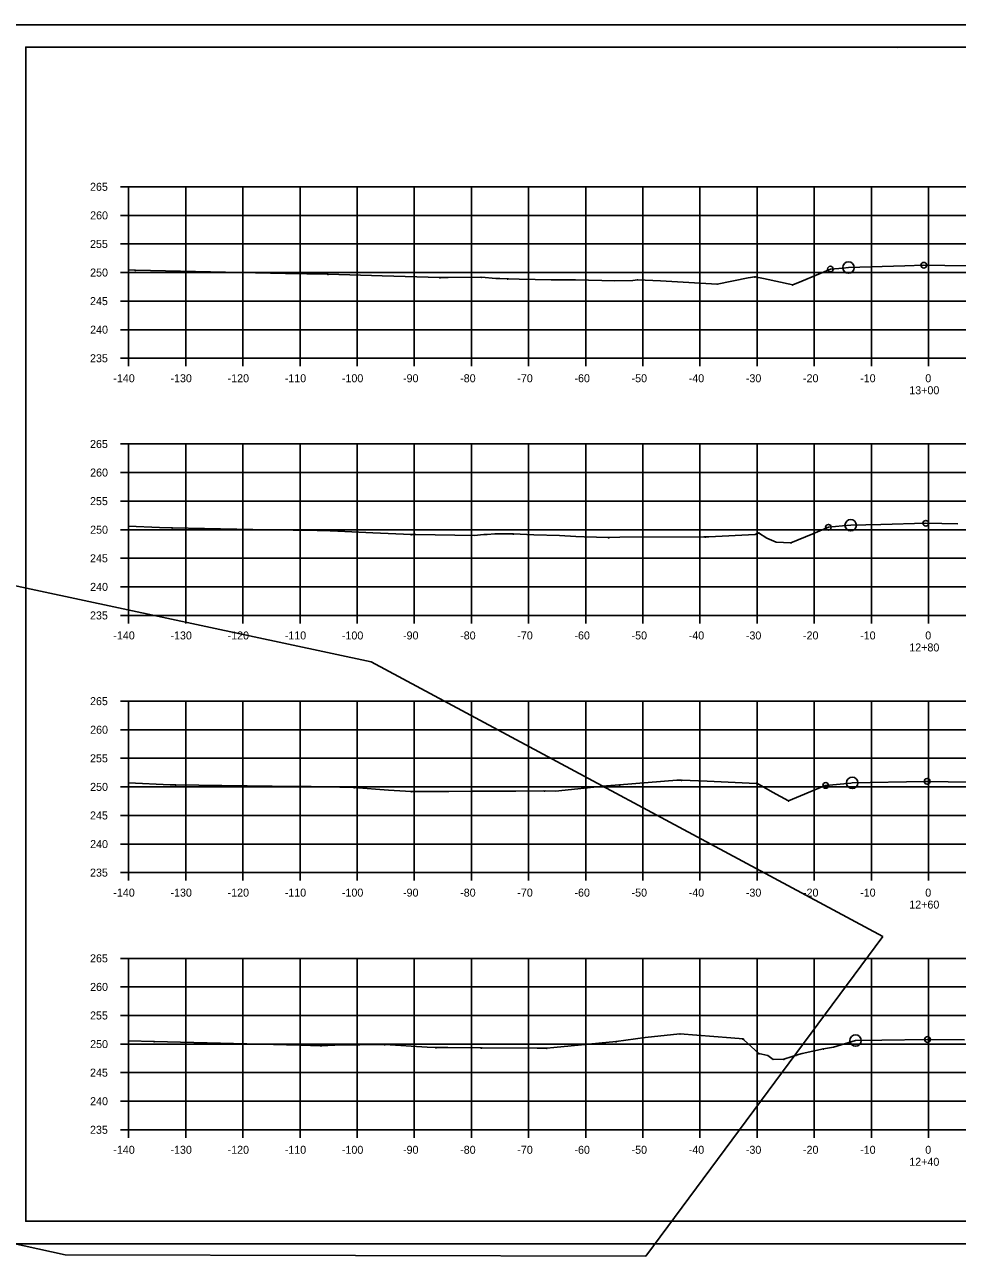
# Model space of a CAD drawing. Extents: x 1300404 to 1323571, y 234004 to 252077.
# Drawn here: x 1315559.1 to 1315722.3, y 244045.5 to 244261.8 of the extents above; entities that cross this region are included whole.
import ezdxf

# ---------------------------------------------------------------- set-up
doc = ezdxf.new("R2010")
doc.units = 0
for name, color, linetype in [('Default', 7, 'Continuous'), ('R_Axis', 7, 'Continuous'), ('R_Axis Annot', 7, 'Continuous'), ('R_Border', 7, 'Continuous'), ('R_Draft', 7, 'Continuous'), ('R_Exist Surface', 7, 'Continuous'), ('R_Flooplain', 7, 'Continuous'), ('R_Grid', 7, 'Continuous'), ('R_No Plot', 7, 'Continuous')]:
    doc.layers.add(name, color=color, linetype=linetype)

msp = doc.modelspace()

# ---------------------------------------------------------------- linework, layer by layer
at = {"layer": 'Default'}
for p, q in [((1315559.28, 244257.94), (1315875.46, 244257.94)), ((1315559.28, 244052.48), (1315559.28, 244257.94)), ((1315875.46, 244052.48), (1315559.28, 244052.48))]:
    msp.add_line(p, q, dxfattribs=at)
at = {"layer": 'R_Axis'}
for p, q in [((1315575.88, 244233.48), (1315577.28, 244233.48)), ((1315577.28, 244203.48), (1315577.28, 244233.48)), ((1315575.88, 244228.48), (1315577.28, 244228.48)), ((1315575.88, 244223.48), (1315577.28, 244223.48)), ((1315575.88, 244218.48), (1315577.28, 244218.48)), ((1315575.88, 244213.48), (1315577.28, 244213.48)), ((1315575.88, 244208.48), (1315577.28, 244208.48)), ((1315575.88, 244203.48), (1315577.28, 244203.48)), ((1315577.28, 244203.48), (1315857.28, 244203.48)), ((1315577.28, 244202.08), (1315577.28, 244203.48)), ((1315587.28, 244202.08), (1315587.28, 244203.48)), ((1315597.28, 244202.08), (1315597.28, 244203.48)), ((1315607.28, 244202.08), (1315607.28, 244203.48)), ((1315617.28, 244202.08), (1315617.28, 244203.48)), ((1315627.28, 244202.08), (1315627.28, 244203.48)), ((1315637.28, 244202.08), (1315637.28, 244203.48)), ((1315647.28, 244202.08), (1315647.28, 244203.48)), ((1315657.28, 244202.08), (1315657.28, 244203.48)), ((1315667.28, 244202.08), (1315667.28, 244203.48)), ((1315677.28, 244202.08), (1315677.28, 244203.48)), ((1315687.28, 244202.08), (1315687.28, 244203.48)), ((1315697.28, 244202.08), (1315697.28, 244203.48)), ((1315707.28, 244202.08), (1315707.28, 244203.48)), ((1315717.28, 244202.08), (1315717.28, 244203.48)), ((1315575.88, 244188.48), (1315577.28, 244188.48)), ((1315577.28, 244158.48), (1315577.28, 244188.48)), ((1315575.88, 244183.48), (1315577.28, 244183.48)), ((1315575.88, 244178.48), (1315577.28, 244178.48)), ((1315575.88, 244173.48), (1315577.28, 244173.48)), ((1315575.88, 244168.48), (1315577.28, 244168.48)), ((1315575.88, 244163.48), (1315577.28, 244163.48)), ((1315575.88, 244158.48), (1315577.28, 244158.48)), ((1315577.28, 244158.48), (1315857.28, 244158.48)), ((1315577.28, 244157.08), (1315577.28, 244158.48)), ((1315587.28, 244157.08), (1315587.28, 244158.48)), ((1315597.28, 244157.08), (1315597.28, 244158.48)), ((1315607.28, 244157.08), (1315607.28, 244158.48)), ((1315617.28, 244157.08), (1315617.28, 244158.48)), ((1315627.28, 244157.08), (1315627.28, 244158.48)), ((1315637.28, 244157.08), (1315637.28, 244158.48)), ((1315647.28, 244157.08), (1315647.28, 244158.48)), ((1315657.28, 244157.08), (1315657.28, 244158.48)), ((1315667.28, 244157.08), (1315667.28, 244158.48)), ((1315677.28, 244157.08), (1315677.28, 244158.48)), ((1315687.28, 244157.08), (1315687.28, 244158.48)), ((1315697.28, 244157.08), (1315697.28, 244158.48)), ((1315707.28, 244157.08), (1315707.28, 244158.48)), ((1315717.28, 244157.08), (1315717.28, 244158.48)), ((1315575.88, 244143.48), (1315577.28, 244143.48)), ((1315577.28, 244113.48), (1315577.28, 244143.48)), ((1315575.88, 244138.48), (1315577.28, 244138.48)), ((1315575.88, 244133.48), (1315577.28, 244133.48)), ((1315575.88, 244128.48), (1315577.28, 244128.48)), ((1315575.88, 244123.48), (1315577.28, 244123.48)), ((1315575.88, 244118.48), (1315577.28, 244118.48)), ((1315575.88, 244113.48), (1315577.28, 244113.48)), ((1315577.28, 244113.48), (1315857.28, 244113.48)), ((1315577.28, 244112.08), (1315577.28, 244113.48)), ((1315587.28, 244112.08), (1315587.28, 244113.48)), ((1315597.28, 244112.08), (1315597.28, 244113.48)), ((1315607.28, 244112.08), (1315607.28, 244113.48)), ((1315617.28, 244112.08), (1315617.28, 244113.48)), ((1315627.28, 244112.08), (1315627.28, 244113.48)), ((1315637.28, 244112.08), (1315637.28, 244113.48)), ((1315647.28, 244112.08), (1315647.28, 244113.48)), ((1315657.28, 244112.08), (1315657.28, 244113.48)), ((1315667.28, 244112.08), (1315667.28, 244113.48)), ((1315677.28, 244112.08), (1315677.28, 244113.48)), ((1315687.28, 244112.08), (1315687.28, 244113.48)), ((1315697.28, 244112.08), (1315697.28, 244113.48)), ((1315707.28, 244112.08), (1315707.28, 244113.48)), ((1315717.28, 244112.08), (1315717.28, 244113.48)), ((1315575.88, 244098.48), (1315577.28, 244098.48)), ((1315577.28, 244068.48), (1315577.28, 244098.48)), ((1315575.88, 244093.48), (1315577.28, 244093.48)), ((1315575.88, 244088.48), (1315577.28, 244088.48)), ((1315575.88, 244083.48), (1315577.28, 244083.48)), ((1315575.88, 244078.48), (1315577.28, 244078.48)), ((1315575.88, 244073.48), (1315577.28, 244073.48)), ((1315575.88, 244068.48), (1315577.28, 244068.48)), ((1315577.28, 244068.48), (1315857.28, 244068.48)), ((1315577.28, 244067.08), (1315577.28, 244068.48)), ((1315587.28, 244067.08), (1315587.28, 244068.48)), ((1315597.28, 244067.08), (1315597.28, 244068.48)), ((1315607.28, 244067.08), (1315607.28, 244068.48)), ((1315617.28, 244067.08), (1315617.28, 244068.48)), ((1315627.28, 244067.08), (1315627.28, 244068.48)), ((1315637.28, 244067.08), (1315637.28, 244068.48)), ((1315647.28, 244067.08), (1315647.28, 244068.48)), ((1315657.28, 244067.08), (1315657.28, 244068.48)), ((1315667.28, 244067.08), (1315667.28, 244068.48)), ((1315677.28, 244067.08), (1315677.28, 244068.48)), ((1315687.28, 244067.08), (1315687.28, 244068.48)), ((1315697.28, 244067.08), (1315697.28, 244068.48)), ((1315707.28, 244067.08), (1315707.28, 244068.48)), ((1315717.28, 244067.08), (1315717.28, 244068.48))]:
    msp.add_line(p, q, dxfattribs=at)
at = {"layer": 'R_Border'}
for p, q in [((1315711.8, 244257.68), (1315711.8, 244257.68)), ((1315711.8, 244257.68), (1315711.8, 244257.68)), ((1315559.28, 244052.48), (1315559.28, 244052.48))]:
    msp.add_line(p, q, dxfattribs=at)
at = {"layer": 'R_Draft'}
for points in [[(1315578.48, 244218.92), (1315578.53, 244218.82), (1315578.43, 244218.82)], [(1315612.18, 244218.23), (1315612.23, 244218.13), (1315612.13, 244218.13)], [(1315639.02, 244217.73), (1315639.07, 244217.63), (1315638.97, 244217.63)], [(1315686.89, 244217.78), (1315686.94, 244217.68), (1315686.84, 244217.68)], [(1315631.78, 244217.65), (1315631.83, 244217.55), (1315631.73, 244217.55)], [(1315643.59, 244217.42), (1315643.64, 244217.32), (1315643.54, 244217.32)], [(1315666.36, 244217.28), (1315666.41, 244217.18), (1315666.31, 244217.18)], [(1315680.29, 244216.52), (1315680.34, 244216.42), (1315680.24, 244216.42)], [(1315693.51, 244216.37), (1315693.56, 244216.27), (1315693.46, 244216.27)], [(1315584.89, 244173.85), (1315584.94, 244173.75), (1315584.84, 244173.75)], [(1315612.66, 244173.36), (1315612.71, 244173.26), (1315612.61, 244173.26)], [(1315626.72, 244172.7), (1315626.77, 244172.6), (1315626.67, 244172.6)], [(1315644.61, 244172.79), (1315644.66, 244172.69), (1315644.56, 244172.69)], [(1315687.52, 244172.98), (1315687.57, 244172.88), (1315687.47, 244172.88)], [(1315661.32, 244172.15), (1315661.37, 244172.05), (1315661.27, 244172.05)], [(1315678.21, 244172.26), (1315678.26, 244172.16), (1315678.16, 244172.16)], [(1315693.21, 244171.24), (1315693.26, 244171.14), (1315693.16, 244171.14)], [(1315674.06, 244129.72), (1315674.11, 244129.62), (1315674.01, 244129.62)], [(1315687.21, 244129.17), (1315687.26, 244129.07), (1315687.16, 244129.07)], [(1315585.52, 244128.88), (1315585.57, 244128.78), (1315585.47, 244128.78)], [(1315606.86, 244128.62), (1315606.91, 244128.52), (1315606.81, 244128.52)], [(1315616.76, 244128.41), (1315616.81, 244128.31), (1315616.71, 244128.31)], [(1315626.73, 244127.72), (1315626.78, 244127.62), (1315626.68, 244127.62)], [(1315637.37, 244127.76), (1315637.42, 244127.66), (1315637.32, 244127.66)], [(1315650.06, 244127.86), (1315650.11, 244127.76), (1315650.01, 244127.76)], [(1315663.21, 244128.88), (1315663.26, 244128.78), (1315663.16, 244128.78)], [(1315692.79, 244126.11), (1315692.84, 244126.01), (1315692.74, 244126.01)], [(1315581.76, 244083.97), (1315581.81, 244083.87), (1315581.71, 244083.87)], [(1315662.6, 244083.97), (1315662.65, 244083.87), (1315662.55, 244083.87)], [(1315673.78, 244085.33), (1315673.83, 244085.23), (1315673.73, 244085.23)], [(1315684.81, 244084.43), (1315684.86, 244084.33), (1315684.76, 244084.33)], [(1315610.96, 244083.24), (1315611.01, 244083.14), (1315610.91, 244083.14)], [(1315622.11, 244083.44), (1315622.16, 244083.34), (1315622.06, 244083.34)], [(1315631.07, 244082.91), (1315631.12, 244082.81), (1315631.02, 244082.81)], [(1315639.03, 244082.85), (1315639.08, 244082.75), (1315638.98, 244082.75)], [(1315650.48, 244082.83), (1315650.53, 244082.73), (1315650.43, 244082.73)], [(1315687.59, 244081.87), (1315687.64, 244081.77), (1315687.54, 244081.77)], [(1315694.12, 244081.59), (1315694.17, 244081.49), (1315694.07, 244081.49)], [(1315698.88, 244082.69), (1315698.93, 244082.59), (1315698.83, 244082.59)], [(1315691.95, 244080.86), (1315692, 244080.76), (1315691.9, 244080.76)]]:
    msp.add_lwpolyline(points, close=True, dxfattribs=at)
at = {"layer": 'R_Exist Surface'}
for points in [[(1315577.28, 244218.95), (1315578.48, 244218.87), (1315604.76, 244218.32), (1315612.18, 244218.18), (1315621.64, 244217.88), (1315631.78, 244217.6), (1315633.19, 244217.63), (1315639.02, 244217.68), (1315641.54, 244217.46), (1315642.25, 244217.44), (1315643.59, 244217.37), (1315643.78, 244217.36), (1315645.61, 244217.34), (1315651.21, 244217.22), (1315655.49, 244217.23), (1315662.35, 244217.02), (1315665.5, 244217.08), (1315666.36, 244217.23), (1315670.35, 244217), (1315680.29, 244216.47), (1315685.72, 244217.53), (1315686.89, 244217.73), (1315688.41, 244217.43), (1315693.51, 244216.32), (1315695.08, 244216.97), (1315700.1, 244219.08), (1315702.31, 244219.26), (1315703.27, 244219.35), (1315713.11, 244219.67), (1315716.46, 244219.76), (1315727.52, 244219.61)], [(1315577.28, 244174.08), (1315582.68, 244173.84), (1315584.89, 244173.8), (1315601.88, 244173.46), (1315610.26, 244173.33), (1315612.66, 244173.31), (1315620.03, 244172.91), (1315626.72, 244172.65), (1315627.57, 244172.64), (1315637.77, 244172.49), (1315639.45, 244172.62), (1315640.02, 244172.63), (1315641.38, 244172.77), (1315644.61, 244172.74), (1315648.21, 244172.6), (1315652.7, 244172.44), (1315655.55, 244172.28), (1315657, 244172.25), (1315661.32, 244172.1), (1315663.25, 244172.2), (1315677.96, 244172.21), (1315678.21, 244172.21), (1315678.84, 244172.24), (1315686.93, 244172.62), (1315687.52, 244172.93), (1315688.99, 244172), (1315690.64, 244171.3), (1315693.21, 244171.19), (1315697.05, 244172.78), (1315699.75, 244173.9), (1315702.24, 244174.14), (1315703.66, 244174.26), (1315708.93, 244174.41), (1315716.8, 244174.6), (1315722.41, 244174.52)], [(1315577.28, 244129.17), (1315584.54, 244128.84), (1315585.52, 244128.83), (1315593.57, 244128.71), (1315606.86, 244128.57), (1315609.21, 244128.55), (1315616.76, 244128.36), (1315622.74, 244127.91), (1315626.73, 244127.67), (1315633.3, 244127.68), (1315637.37, 244127.71), (1315645.08, 244127.76), (1315650.06, 244127.81), (1315652, 244127.71), (1315660.91, 244128.68), (1315663.21, 244128.83), (1315673.22, 244129.63), (1315674.06, 244129.67), (1315678.53, 244129.49), (1315687.1, 244129.07), (1315687.21, 244129.12), (1315690, 244127.55), (1315692.79, 244126.06), (1315698.81, 244128.53), (1315699.28, 244128.73), (1315703.66, 244129.15), (1315703.93, 244129.18), (1315716.55, 244129.44), (1315717.03, 244129.45), (1315717.54, 244129.44), (1315730.12, 244129.21)], [(1315577.28, 244084.03), (1315581.76, 244083.92), (1315607.26, 244083.29), (1315610.96, 244083.19), (1315613.4, 244083.26), (1315622.11, 244083.39), (1315629.53, 244082.95), (1315631.07, 244082.86), (1315633.13, 244082.89), (1315639.03, 244082.8), (1315648.8, 244082.76), (1315650.48, 244082.78), (1315651.73, 244082.87), (1315662.6, 244083.92), (1315667.67, 244084.63), (1315673.78, 244085.28), (1315682.69, 244084.57), (1315684.81, 244084.38), (1315684.98, 244084.21), (1315687.59, 244081.82), (1315689.13, 244081.46), (1315690.07, 244080.8), (1315691.95, 244080.81), (1315693.44, 244081.28), (1315694.12, 244081.54), (1315695.15, 244081.82), (1315698.88, 244082.64), (1315700.64, 244082.95), (1315704.51, 244084.09), (1315709.1, 244084.15), (1315717.1, 244084.28), (1315723.6, 244084.2)]]:
    msp.add_lwpolyline(points, dxfattribs=at)
at = {"layer": 'R_Flooplain'}
for p, q in [((1315471.31, 244182.06), (1315619.74, 244150.39)), ((1315619.74, 244150.39), (1315709.29, 244102.32)), ((1315709.29, 244102.32), (1315667.79, 244046.34)), ((1315566.18, 244046.62), (1315451.3, 244071.77)), ((1315667.79, 244046.34), (1315566.18, 244046.62))]:
    msp.add_line(p, q, dxfattribs=at)
at = {"layer": 'R_Grid'}
for p, q in [((1315577.28, 244233.48), (1315857.28, 244233.48)), ((1315577.28, 244203.48), (1315577.28, 244233.48)), ((1315587.28, 244203.48), (1315587.28, 244233.48)), ((1315597.28, 244203.48), (1315597.28, 244233.48)), ((1315607.28, 244203.48), (1315607.28, 244233.48)), ((1315617.28, 244203.48), (1315617.28, 244233.48)), ((1315627.28, 244203.48), (1315627.28, 244233.48)), ((1315637.28, 244203.48), (1315637.28, 244233.48)), ((1315647.28, 244203.48), (1315647.28, 244233.48)), ((1315657.28, 244203.48), (1315657.28, 244233.48)), ((1315667.28, 244203.48), (1315667.28, 244233.48)), ((1315677.28, 244203.48), (1315677.28, 244233.48)), ((1315687.28, 244203.48), (1315687.28, 244233.48)), ((1315697.28, 244203.48), (1315697.28, 244233.48)), ((1315707.28, 244203.48), (1315707.28, 244233.48)), ((1315717.28, 244203.48), (1315717.28, 244233.48)), ((1315577.28, 244228.48), (1315857.28, 244228.48)), ((1315577.28, 244223.48), (1315857.28, 244223.48)), ((1315577.28, 244218.48), (1315857.28, 244218.48)), ((1315577.28, 244213.48), (1315857.28, 244213.48)), ((1315577.28, 244208.48), (1315857.28, 244208.48)), ((1315577.28, 244203.48), (1315857.28, 244203.48)), ((1315577.28, 244188.48), (1315857.28, 244188.48)), ((1315577.28, 244158.48), (1315577.28, 244188.48)), ((1315587.28, 244158.48), (1315587.28, 244188.48)), ((1315597.28, 244158.48), (1315597.28, 244188.48)), ((1315607.28, 244158.48), (1315607.28, 244188.48)), ((1315617.28, 244158.48), (1315617.28, 244188.48)), ((1315627.28, 244158.48), (1315627.28, 244188.48)), ((1315637.28, 244158.48), (1315637.28, 244188.48)), ((1315647.28, 244158.48), (1315647.28, 244188.48)), ((1315657.28, 244158.48), (1315657.28, 244188.48)), ((1315667.28, 244158.48), (1315667.28, 244188.48)), ((1315677.28, 244158.48), (1315677.28, 244188.48)), ((1315687.28, 244158.48), (1315687.28, 244188.48)), ((1315697.28, 244158.48), (1315697.28, 244188.48)), ((1315707.28, 244158.48), (1315707.28, 244188.48)), ((1315717.28, 244158.48), (1315717.28, 244188.48)), ((1315577.28, 244183.48), (1315857.28, 244183.48)), ((1315577.28, 244178.48), (1315857.28, 244178.48)), ((1315577.28, 244173.48), (1315857.28, 244173.48)), ((1315577.28, 244168.48), (1315857.28, 244168.48)), ((1315577.28, 244163.48), (1315857.28, 244163.48)), ((1315577.28, 244158.48), (1315857.28, 244158.48)), ((1315577.28, 244143.48), (1315857.28, 244143.48)), ((1315577.28, 244113.48), (1315577.28, 244143.48)), ((1315587.28, 244113.48), (1315587.28, 244143.48)), ((1315597.28, 244113.48), (1315597.28, 244143.48)), ((1315607.28, 244113.48), (1315607.28, 244143.48)), ((1315617.28, 244113.48), (1315617.28, 244143.48)), ((1315627.28, 244113.48), (1315627.28, 244143.48)), ((1315637.28, 244113.48), (1315637.28, 244143.48)), ((1315647.28, 244113.48), (1315647.28, 244143.48)), ((1315657.28, 244113.48), (1315657.28, 244143.48)), ((1315667.28, 244113.48), (1315667.28, 244143.48)), ((1315677.28, 244113.48), (1315677.28, 244143.48)), ((1315687.28, 244113.48), (1315687.28, 244143.48)), ((1315697.28, 244113.48), (1315697.28, 244143.48)), ((1315707.28, 244113.48), (1315707.28, 244143.48)), ((1315717.28, 244113.48), (1315717.28, 244143.48)), ((1315577.28, 244138.48), (1315857.28, 244138.48)), ((1315577.28, 244133.48), (1315857.28, 244133.48)), ((1315577.28, 244128.48), (1315857.28, 244128.48)), ((1315577.28, 244123.48), (1315857.28, 244123.48)), ((1315577.28, 244118.48), (1315857.28, 244118.48)), ((1315577.28, 244113.48), (1315857.28, 244113.48)), ((1315577.28, 244098.48), (1315857.28, 244098.48)), ((1315577.28, 244068.48), (1315577.28, 244098.48)), ((1315587.28, 244068.48), (1315587.28, 244098.48)), ((1315597.28, 244068.48), (1315597.28, 244098.48)), ((1315607.28, 244068.48), (1315607.28, 244098.48)), ((1315617.28, 244068.48), (1315617.28, 244098.48)), ((1315627.28, 244068.48), (1315627.28, 244098.48)), ((1315637.28, 244068.48), (1315637.28, 244098.48)), ((1315647.28, 244068.48), (1315647.28, 244098.48)), ((1315657.28, 244068.48), (1315657.28, 244098.48)), ((1315667.28, 244068.48), (1315667.28, 244098.48)), ((1315677.28, 244068.48), (1315677.28, 244098.48)), ((1315687.28, 244068.48), (1315687.28, 244098.48)), ((1315697.28, 244068.48), (1315697.28, 244098.48)), ((1315707.28, 244068.48), (1315707.28, 244098.48)), ((1315717.28, 244068.48), (1315717.28, 244098.48)), ((1315577.28, 244093.48), (1315857.28, 244093.48)), ((1315577.28, 244088.48), (1315857.28, 244088.48)), ((1315577.28, 244083.48), (1315857.28, 244083.48)), ((1315577.28, 244078.48), (1315857.28, 244078.48)), ((1315577.28, 244073.48), (1315857.28, 244073.48)), ((1315577.28, 244068.48), (1315857.28, 244068.48))]:
    msp.add_line(p, q, dxfattribs=at)
at = {"layer": 'R_No Plot'}
for p, q in [((1315546.87, 244261.84), (1315880.21, 244261.84)), ((1315546.87, 244048.51), (1315880.21, 244048.51)), ((1315546.87, 244048.5), (1315880.21, 244048.5))]:
    msp.add_line(p, q, dxfattribs=at)
for points in [[(1315546.87, 244261.84), (1315880.21, 244261.84), (1315880.21, 244048.5), (1315546.87, 244048.5)], [(1315793.2, 244257.94), (1315793.2, 244248.06), (1315828.93, 244248.06), (1315828.93, 244245.14), (1315852.13, 244245.14), (1315852.13, 244223.03), (1315875.46, 244223.03), (1315875.46, 244052.48), (1315559.28, 244052.48), (1315559.28, 244257.94)], [(1315546.87, 244048.5), (1315880.21, 244048.5), (1315880.21, 243835.16), (1315546.87, 243835.16)]]:
    msp.add_lwpolyline(points, close=True, dxfattribs=at)
for centre, radius in [((1315703.27, 244219.35), 1), ((1315716.46, 244219.76), 0.5), ((1315700.1, 244219.08), 0.5), ((1315703.66, 244174.26), 1), ((1315716.8, 244174.6), 0.5), ((1315699.75, 244173.9), 0.5), ((1315699.28, 244128.73), 0.5), ((1315703.93, 244129.18), 1), ((1315717.03, 244129.45), 0.5), ((1315704.51, 244084.09), 1), ((1315717.1, 244084.28), 0.5)]:
    msp.add_circle(centre, radius, dxfattribs=at)

# ---------------------------------------------------------------- texts
at = {"layer": 'R_Axis'}
for p in [(1315577.28, 244203.48), (1315577.28, 244158.48), (1315577.28, 244113.48), (1315577.28, 244068.48)]:
    msp.add_text('-', height=0.0001, dxfattribs=at).set_placement(p)
at = {"layer": 'R_Axis Annot'}
for s, p in [('265', (1315570.53, 244232.78)), ('260', (1315570.55, 244227.78)), ('255', (1315570.53, 244222.78)), ('250', (1315570.55, 244217.78)), ('245', (1315570.53, 244212.78)), ('240', (1315570.55, 244207.78)), ('235', (1315570.53, 244202.78)), ('-140', (1315574.61, 244199.28)), ('-130', (1315584.61, 244199.28)), ('-120', (1315594.61, 244199.28)), ('-110', (1315604.61, 244199.28)), ('-100', (1315614.61, 244199.28)), ('-90', (1315625.31, 244199.28)), ('-80', (1315635.31, 244199.28)), ('-70', (1315645.31, 244199.28)), ('-60', (1315655.31, 244199.28)), ('-50', (1315665.31, 244199.28)), ('-40', (1315675.31, 244199.28)), ('-30', (1315685.31, 244199.28)), ('-20', (1315695.31, 244199.28)), ('-10', (1315705.31, 244199.28)), ('0', (1315716.71, 244199.28)), ('13+00', (1315713.91, 244197.18)), ('265', (1315570.53, 244187.78)), ('260', (1315570.55, 244182.78)), ('255', (1315570.53, 244177.78)), ('250', (1315570.55, 244172.78)), ('245', (1315570.53, 244167.78)), ('240', (1315570.55, 244162.78)), ('235', (1315570.53, 244157.78)), ('-140', (1315574.61, 244154.28)), ('-130', (1315584.61, 244154.28)), ('-120', (1315594.61, 244154.28)), ('-110', (1315604.61, 244154.28)), ('-100', (1315614.61, 244154.28)), ('-90', (1315625.31, 244154.28)), ('-80', (1315635.31, 244154.28)), ('-70', (1315645.31, 244154.28)), ('-60', (1315655.31, 244154.28)), ('-50', (1315665.31, 244154.28)), ('-40', (1315675.31, 244154.28)), ('-30', (1315685.31, 244154.28)), ('-20', (1315695.31, 244154.28)), ('-10', (1315705.31, 244154.28)), ('0', (1315716.71, 244154.28)), ('12+80', (1315713.91, 244152.18)), ('265', (1315570.53, 244142.78)), ('260', (1315570.55, 244137.78)), ('255', (1315570.53, 244132.78)), ('250', (1315570.55, 244127.78)), ('245', (1315570.53, 244122.78)), ('240', (1315570.55, 244117.78)), ('235', (1315570.53, 244112.78)), ('-140', (1315574.61, 244109.28)), ('-130', (1315584.61, 244109.28)), ('-120', (1315594.61, 244109.28)), ('-110', (1315604.61, 244109.28)), ('-100', (1315614.61, 244109.28)), ('-90', (1315625.31, 244109.28)), ('-80', (1315635.31, 244109.28)), ('-70', (1315645.31, 244109.28)), ('-60', (1315655.31, 244109.28)), ('-50', (1315665.31, 244109.28)), ('-40', (1315675.31, 244109.28)), ('-30', (1315685.31, 244109.28)), ('-20', (1315695.31, 244109.28)), ('-10', (1315705.31, 244109.28)), ('0', (1315716.71, 244109.28)), ('12+60', (1315713.91, 244107.18)), ('265', (1315570.53, 244097.78)), ('260', (1315570.55, 244092.78)), ('255', (1315570.53, 244087.78)), ('250', (1315570.55, 244082.78)), ('245', (1315570.53, 244077.78)), ('240', (1315570.55, 244072.78)), ('235', (1315570.53, 244067.78)), ('-140', (1315574.61, 244064.28)), ('-130', (1315584.61, 244064.28)), ('-120', (1315594.61, 244064.28)), ('-110', (1315604.61, 244064.28)), ('-100', (1315614.61, 244064.28)), ('-90', (1315625.31, 244064.28)), ('-80', (1315635.31, 244064.28)), ('-70', (1315645.31, 244064.28)), ('-60', (1315655.31, 244064.28)), ('-50', (1315665.31, 244064.28)), ('-40', (1315675.31, 244064.28)), ('-30', (1315685.31, 244064.28)), ('-20', (1315695.31, 244064.28)), ('-10', (1315705.31, 244064.28)), ('0', (1315716.71, 244064.28)), ('12+40', (1315713.91, 244062.18))]:
    msp.add_text(s, height=1.4, dxfattribs=at).set_placement(p)

doc.saveas('drawing.dxf')
